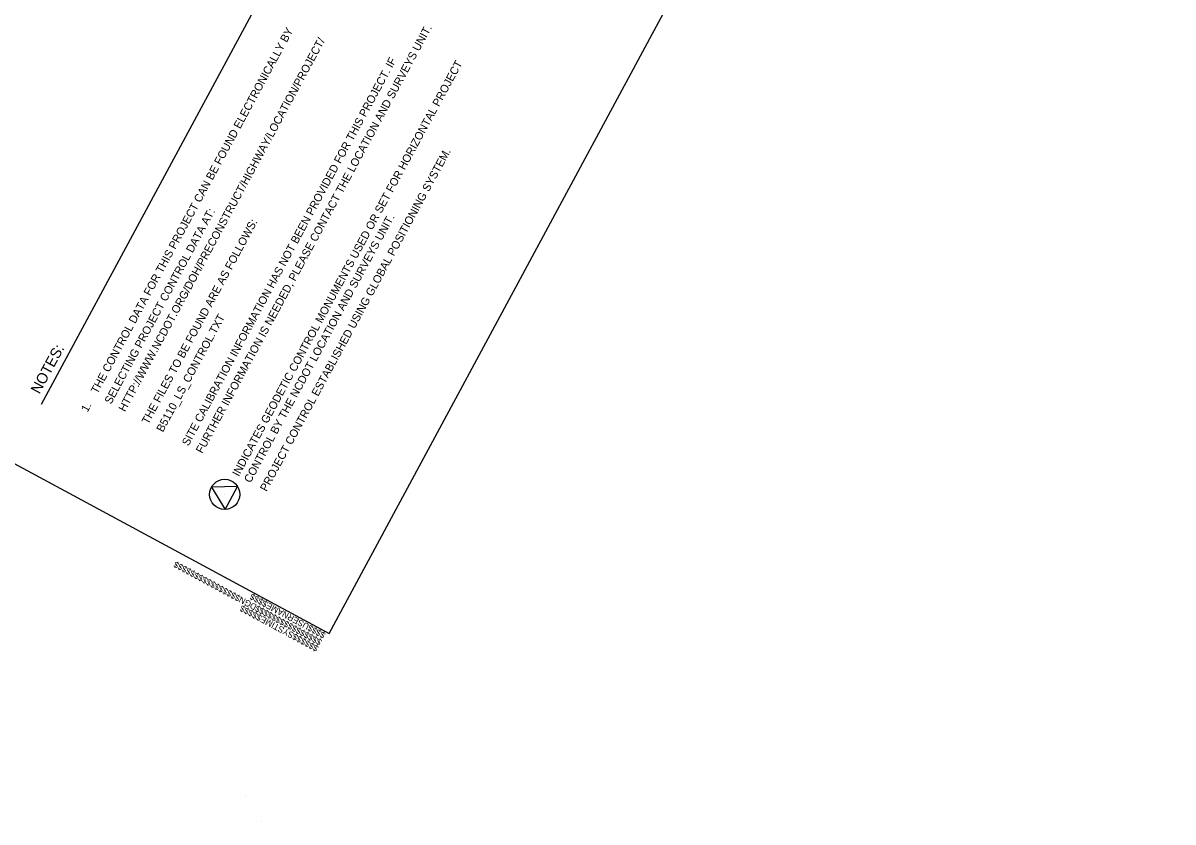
# Model space of a CAD drawing. Extents: x 1376594 to 1378079, y 762010 to 763753.
# Drawn here: x 1377235 to 1378079, y 762010 to 762595 of the extents above; entities that cross this region are included whole.
import ezdxf

# ---------------------------------------------------------------- set-up
doc = ezdxf.new("R2010")
doc.units = 0
for name, color, linetype in [('CTL NGS Horizontal and Vertical CELL', 7, 'Continuous'), ('CTL Sheet Border CELL', 7, 'Continuous'), ('CTL Sheet Notes CELL', 7, 'Continuous')]:
    doc.layers.add(name, color=color, linetype=linetype)

# ---------------------------------------------------------------- blocks, each defined once
blk = doc.blocks.new('CTL NGS HORIZONTAL AND VERTICAL')
at = {"layer": 'CTL NGS Horizontal and Vertical CELL'}
blk.add_line((0, 0), (0, 0), dxfattribs=at)
blk.add_lwpolyline([(-0.0638, -0.0372), (0.0638, -0.0372), (0, 0.0737)], close=True, dxfattribs=at)
blk.add_circle((0, -0.0001), 0.0738, dxfattribs=at)

msp = doc.modelspace()

# ---------------------------------------------------------------- linework, layer by layer
at = {"layer": 'CTL Sheet Border CELL'}
for p, q in [((1377459.94, 762147.84), (1377459.94, 762147.84)), ((1377459.94, 762147.84), (1377459.94, 762147.84)), ((1377459.94, 762147.84), (1377459.94, 762147.84)), ((1377459.94, 762147.84), (1377459.94, 762147.84)), ((1377459.94, 762147.84), (1377459.94, 762147.84)), ((1377459.94, 762147.84), (1377459.94, 762147.84)), ((1377459.94, 762147.84), (1377459.94, 762147.84)), ((1377459.94, 762147.84), (1377459.94, 762147.84)), ((1377459.94, 762147.84), (1377459.94, 762147.84)), ((1377459.94, 762147.84), (1377459.94, 762147.84)), ((1377459.94, 762147.84), (1377459.94, 762147.84)), ((1377398.35, 762028.91), (1377398.35, 762028.91)), ((1377410.17, 762009.7), (1377410.17, 762009.7))]:
    msp.add_line(p, q, dxfattribs=at)
msp.add_lwpolyline([(1377275.23, 763729.25), (1376656.26, 762581.12), (1377459.94, 762147.84), (1378078.92, 763295.97)], close=True, dxfattribs=at)
msp.add_lwpolyline([(1377475.42, 762176.54), (1377475.42, 762176.54)], dxfattribs=at)
msp.add_lwpolyline([(1377475.42, 762176.54), (1377475.42, 762176.54)], dxfattribs=at)
at = {"layer": 'CTL Sheet Notes CELL'}
msp.add_line((1377248.9, 762316.02), (1377444.79, 762679.37), dxfattribs=at)

# ---------------------------------------------------------------- block references
at = {"layer": 'CTL NGS Horizontal and Vertical CELL', "xscale": 150, "yscale": 150, "rotation": -58.36276881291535}
msp.add_blockref('CTL NGS HORIZONTAL AND VERTICAL', (1377383.23, 762249.84), dxfattribs=at)

# ---------------------------------------------------------------- texts
at = {"layer": 'CTL Sheet Border CELL'}
for s, p in [('$$$$$$$$$$$$$$$$DGN$$$$$$$$$$$$$$$$', (1377454.99, 762142.97)), ('$$$$USERNAME$$$$', (1377457.69, 762148)), ('$$$$$$SYSTIME$$$$$', (1377452.49, 762138.34))]:
    msp.add_text(s, height=4.5652, rotation=151.67024, dxfattribs=at).set_placement(p)
at = {"layer": 'CTL Sheet Notes CELL'}
for s, height, rotation, p in [('1.    THE CONTROL DATA FOR THIS PROJECT CAN BE FOUND ELECTRONICALLY BY', 5.8696, 61.67024, (1377282.62, 762309.69)), ('FURTHER INFORMATION IS NEEDED, PLEASE CONTACT THE LOCATION AND SURVEYS UNIT.', 5.8696, 61.67024, (1377366.84, 762279.4)), ('HTTP://WWW.NCDOT.ORG/DOH/PRECONSTRUCT/HIGHWAY/LOCATION/PROJECT/', 5.8696, 61.67024, (1377310.11, 762309.98)), ('SITE CALIBRATION INFORMATION HAS NOT BEEN PROVIDED FOR THIS PROJECT. IF ', 5.8696, 61.67024, (1377356.66, 762284.89)), ('INDICATES GEODETIC CONTROL MONUMENTS USED OR SET FOR HORIZONTAL PROJECT', 5.8696, 61.56499, (1377393.61, 762262.5)), ('PROJECT CONTROL ESTABLISHED USING GLOBAL POSITIONING SYSTEM.', 5.8696, 61.56499, (1377413.94, 762251.49)), ('SELECTING PROJECT CONTROL DATA AT:', 5.8696, 61.67024, (1377299.86, 762315.51)), ('CONTROL BY THE NCDOT LOCATION AND SURVEYS UNIT.', 5.8696, 61.56499, (1377402.19, 762257.82)), ('THE FILES TO BE FOUND ARE AS FOLLOWS:', 5.8696, 61.67024, (1377327.18, 762300.78)), ('B5110_LS_CONTROL.TXT', 5.8696, 61.67024, (1377337.91, 762295)), ('NOTES:', 7.826, 61.56499, (1377247.32, 762322.93))]:
    msp.add_text(s, height=height, rotation=rotation, dxfattribs=at).set_placement(p)

doc.saveas('drawing.dxf')
